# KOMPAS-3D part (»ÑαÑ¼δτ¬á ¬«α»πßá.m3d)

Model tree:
1. Эскиз:1
2. Операция выдавливания:1
     Расстояние 1 = 64; Расстояние 2 = 64
3. Эскиз:2
4. Вырезать элемент выдавливания:1
     Расстояние 2 = 64; Расстояние 1 = 64

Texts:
  Сплав АЛ8  ГОСТ 1583-93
